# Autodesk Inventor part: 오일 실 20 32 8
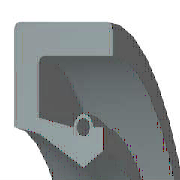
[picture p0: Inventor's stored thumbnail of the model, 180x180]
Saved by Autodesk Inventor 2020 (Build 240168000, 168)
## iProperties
Created: 2012-02
Part Number: 오일 실 20 32 8
Material: 고무
Description: 오일 실 - 스프링 장착, 금속 케이스 SM
Document SubType Name: Modeling
Standard: JIS B 2402
Designer: mdu-01
Standards Organization: JIS
Language: ko-KR
Size Designation: 20 32 8 A
Categories: <MemberInstance><Categories><Category DisplayName="샤프트 부품" InternalName="7f7aeb1f-a693-4053-b835-cee3144e0d98" Mnemonic="SHFT"><Category DisplayName="실링" Intern
Density: 0.93 g/cm^3
Appearance: Rubber-Black
IsCustomPart: 1
Author: mdu-01
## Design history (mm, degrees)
body "Solid1"
revolve "회전1" stored, may be unused: angle "d33" = 360 deg
fillet "모깎기1" dims "d34" = 0.4 (= 0.05 x b)
chamfer "모따기1" distance "d35" = 0.8 (= 0.1 x b); stored, may be unused: second distance "d36" = 0.4 (= 0.05 x b), angle "d41" = 45 deg
sketch "스케치2"
  geometry: L1 (11.457, -5.895)-(12.021, -8); L2 (10.857, -5.2)-(11.457, -5.895); L3 (10, -2)-(10.857, -5.2); L4 (10.8, -1)-(10, -2); L5 (12.141, -1)-(10.8, -1); L6 (12.141, -1.8)-(12.141, -1); L7 (12.141, -6)-(12.141, -3.4); L8 (13.6, -6)-(12.141, -6); L9 (14.8, -2)-(13.6, -6); L10 (14.8, 0)-(14.8, -2); L11 (16, 0)-(14.8, 0); L12 (16, -8)-(16, 0); L13 (12.021, -8)-(16, -8); L14 (0, -9.6)-(0, 1.6) reference; L15 (28, 0)-(14, 0) reference; A1 r 0.8 centre (12.141, -2.6) between (12.141, -3.4) and (12.141, -1.8)
  constraints: 26 end point, 4 horizontal, 4 vertical, 2 point on circle, 1 centre point, 1 collinear, 1 parallel
  dimensions: "d2" = 8 distance of L12.start L11.start (= b); "d4" = 1 vertical distance of L10.start L5.start (= 0.125 x b); "d6" = 1.2 distance of L11.start L10.start (= 0.1 x dd - 0.1 x Diam); "d8" = 2 distance of L10.start L9.start (= 0.25 x b); "d10" = 2 vertical distance of L8.start L1.end (= 0.25 x b); "d12" = 1.2 horizontal distance of L9.start L8.start (= 0.1 x dd - 0.1 x Diam); "d14" = 0.8 radius of A1 (= 0.1 x b); "d16" = 0 horizontal distance of A1.centre L7.end; "d18" = 0.8 distance of L6.start L5.start (= 0.1 x b); "d20" = 0.8 horizontal distance of L4.start L3.start (= 0.0666667 x dd - 0.0666667 x Diam); "d22" = 0.12 horizontal distance of L7.start L1.end (= 0.01 x dd - 0.01 x Diam); "d24" = 1 vertical distance of L4.start L3.start (= 0.125 x b); "d26" = 3.2 vertical distance of L3.start L2.start (= 0.4 x b); "d28" = 0.85714 horizontal distance of L3.start L2.start (= 0.0714286 x dd - 0.0714286 x Diam); "d30" = 2.10526 vertical distance of L1.start L1.end (= 0.263158 x b); "d32" = 0.6 horizontal distance of L2.start L1.start (= 0.05 x dd - 0.05 x Diam); "d37" = 0 distance between parallel lines of L15 L11; "d38" = 16 distance between parallel lines of L14 L12 (= 0.5 x dd); "d39" = 10 distance from line of L14 L3.start (= 0.5 x Diam)
other parameters: "dd" = 32 [user parameter; used in 7 equation terms], "b" = 8 [user parameter; used in 12 equation terms], "d1" = 8 (derived), "d3" = 1 (derived), "d5" = 2 (derived), "d7" = 2 (derived), "d9" = 2 (derived), "d11" = 2 (derived), "d13" = 0.8 (derived), "d15" = 0 (derived), "d17" = 0.8 (derived), "d19" = 1.33333 (derived), "d21" = 0.2 (derived), "d23" = 1 (derived), "d25" = 3.2 (derived), "d27" = 1.42857 (derived), "d29" = 2.10526 (derived), "d31" = 1 (derived), "d40" = 0
